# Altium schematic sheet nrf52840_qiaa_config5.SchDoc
size A4; Revision: 1.3; SheetNumber: 1; SheetTotal: 1; DrawnBy: RUBR; DocumentSize: A4; RefLayoutTitle: Reference Layout Config. 5: VDD supply, DCDC, USB, NFC; Device: nRF52840-QIAA
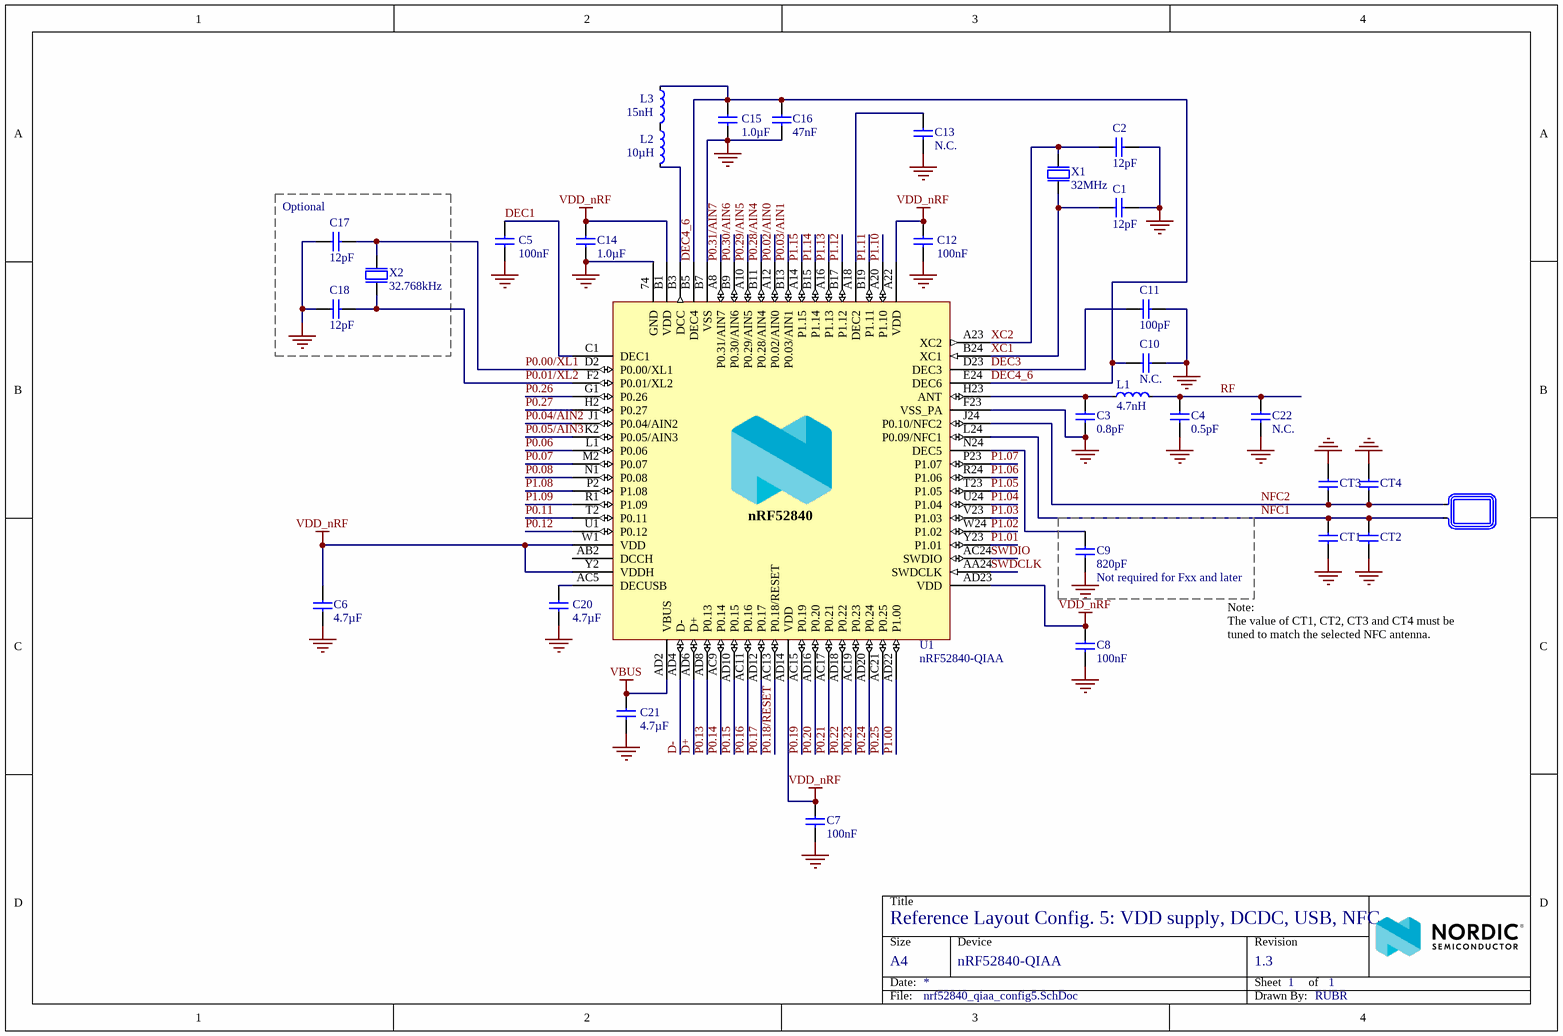
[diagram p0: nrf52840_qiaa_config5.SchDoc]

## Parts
A1  NFC Antenna  [TP_2x1mm_TH]  (value not drawn)  (no BOM)
C1  12pF  [CAPC1005X04L]
C2  12pF  [CAPC1005X04L]
C3  0.8pF  [CAPC1005X04L]
C4  0.5pF  [CAPC1005X04L]
C5  100nF  [CAPC1005X04L]
C6  4.7µF  [CAPC1608X06L]
C7  100nF  [CAPC1005X04L]
C8  100nF  [CAPC1005X04L]
C9  820pF  Assembly: Not required for Fxx and later  [CAPC1005X04L]
C10  N.C.  [CAPC1005X04L]
C11  100pF  [CAPC1005X04L]
C12  100nF  [CAPC1005X04L]
C13  N.C.  [CAPC1005X04L]
C14  1.0µF  [CAPC1608X06L]
C15  1.0µF  [CAPC1608X06L]
C16  47nF  [CAPC1005X04L]
C17  12pF  [CAPC1005X04L]
C18  12pF  [CAPC1005X04L]
C20  4.7µF  [CAPC1608X06L]
C21  4.7µF  [CAPC1608X06L]
C22  N.C.  [CAPC1005X04L]
CT1  Antenna dependent  [CAPC1005X04L]  (value not drawn)
CT2  Antenna dependent  [CAPC1005X04L]  (value not drawn)
CT3  Antenna dependent  [CAPC1005X04L]  (value not drawn)
CT4  Antenna dependent  [CAPC1005X04L]  (value not drawn)
L1  4.7nH  [INDC1005X04L]
L2  10µH  [INDC1608X06L]
L3  15nH  [INDC1005X04L]
U1  nRF52840-QIAA  [AQFN50P700X700X85_HS-74N]
X1  32MHz  [BT-XTAL_2016]
X2  32.768kHz  [XTAL_3215]

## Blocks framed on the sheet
Optional: C17 C18 X2

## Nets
GND: C1.2 C2.2 C3.1 C4.1 C5.2 C6.2 C7.2 C8.2 C9.2 C10.1 C11.2 C12.2 C13.2 C14.2 C15.1 C16.2 C17.2 C18.2 C20.2 C21.2 C22.2 CT1.2 CT2.2 CT3.1 CT4.1 U1.74(GND) U1.B7(VSS) U1.F23(VSS_PA) X1.2(GND) X1.4(GND)
VBUS: C21.1 U1.AD2(VBUS)
VDD_nRF: C6.1 C7.1 C8.1 C12.1 C14.1 U1.A22(VDD) U1.AD14(VDD) U1.AD23(VDD) U1.B1(VDD) U1.W1(VDD) U1.Y2(VDDH)
D+: U1.AD6(D+)
D-: U1.AD4(D-)
DEC1: C5.1 U1.C1(DEC1)
DEC3: C11.1 U1.D23(DEC3)
DEC4_6: C10.2 C15.2 C16.1 L3.1 U1.B5(DEC4) U1.E24(DEC6)
NFC1: A1.2 CT1.1 CT2.1 U1.L24(P0.09/NFC1)
NFC2: A1.1 CT3.2 CT4.2 U1.J24(P0.10/NFC2)
P0.00/XL1: C17.1 U1.D2(P0.00/XL1) X2.1(inp)
P0.01/XL2: C18.1 U1.F2(P0.01/XL2) X2.2(out)
P0.02/AIN0: U1.A12(P0.02/AIN0)
P0.03/AIN1: U1.B13(P0.03/AIN1)
P0.04/AIN2: U1.J1(P0.04/AIN2)
P0.05/AIN3: U1.K2(P0.05/AIN3)
P0.06: U1.L1(P0.06)
P0.07: U1.M2(P0.07)
P0.08: U1.N1(P0.08)
P0.11: U1.T2(P0.11)
P0.12: U1.U1(P0.12)
P0.13: U1.AD8(P0.13)
P0.14: U1.AC9(P0.14)
P0.15: U1.AD10(P0.15)
P0.16: U1.AC11(P0.16)
P0.17: U1.AD12(P0.17)
P0.18/RESET: U1.AC13(P0.18/RESET)
P0.19: U1.AC15(P0.19)
P0.20: U1.AD16(P0.20)
P0.21: U1.AC17(P0.21)
P0.22: U1.AD18(P0.22)
P0.23: U1.AC19(P0.23)
P0.24: U1.AD20(P0.24)
P0.25: U1.AC21(P0.25)
P0.26: U1.G1(P0.26)
P0.27: U1.H2(P0.27)
P0.28/AIN4: U1.B11(P0.28/AIN4)
P0.29/AIN5: U1.A10(P0.29/AIN5)
P0.30/AIN6: U1.B9(P0.30/AIN6)
P0.31/AIN7: U1.A8(P0.31/AIN7)
P1.00: U1.AD22(P1.00)
P1.01: U1.Y23(P1.01)
P1.02: U1.W24(P1.02)
P1.03: U1.V23(P1.03)
P1.04: U1.U24(P1.04)
P1.05: U1.T23(P1.05)
P1.06: U1.R24(P1.06)
P1.07: U1.P23(P1.07)
P1.08: U1.P2(P1.08)
P1.09: U1.R1(P1.09)
P1.10: U1.A20(P1.10)
P1.11: U1.B19(P1.11)
P1.12: U1.B17(P1.12)
P1.13: U1.A16(P1.13)
P1.14: U1.B15(P1.14)
P1.15: U1.A14(P1.15)
RF: C4.2 C22.1 L1.2
SWDCLK: U1.AA24(SWDCLK)
SWDIO: U1.AC24(SWDIO)
XC1: C1.1 U1.B24(XC1) X1.1(inp)
XC2: C2.1 U1.A23(XC2) X1.3(out)
NetC3_2: C3.2 L1.1 U1.H23(ANT)
NetC9_1: C9.1 U1.N24(DEC5)
NetC13_1: C13.1 U1.A18(DEC2)
NetC20_1: C20.1 U1.AC5(DECUSB)
NetL2_1: L2.1 L3.2
NetL2_2: L2.2 U1.B3(DCC)

Not connected (* = marked no-connect by the designer): U1 AB2(DCCH)

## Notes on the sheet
- Note:
  The value of CT1, CT2, CT3 and CT4 must be tuned to match the selected NFC antenna.

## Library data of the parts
A1 = NFC_ANT_TP: Pad Count: 2
C1 C2 C17 C18 = C0402-12p: Capacitor, NP0, ±2%; Pad Count: 2
C3 = C0402-0.8p: Capacitor, NP0, ±10%; Pad Count: 2
C4 = C0402-0.5p: Capacitor, NP0, ±10%; Pad Count: 2
C5 C7 C8 C12 = C0402-100n: Capacitor, X7R, ±10%; Pad Count: 2
C6 C20 = C0603-4µ7-6.3V-X7R: Capacitor, X7R, ±10%; Pad Count: 2
C9 = C0402-820p: Capacitor, NP0, ±5%; Pad Count: 2
C10 C13 C22 = C0402-N.C.: Not mounted; Pad Count: 2; Assembly: Not mounted
C11 = C0402-100p: Capacitor, NP0, ±5%; Pad Count: 2
C14 C15 = C0603-1µ0: Capacitor, X7R, ±10%; Pad Count: 2
C16 = C0402-47n: Capacitor, X7R, ±10%; Pad Count: 2
C21 = C0603-4µ7-10V-X7S: Capacitor, X7S, ±10%; Pad Count: 2
CT1-CT4 = C0402-TBD: Capacitor, NP0, ±5%; Pad Count: 2
L1 = L0402-4n7: High frequency chip inductor ±5%; Pad Count: 2
L2 = L0603-10µ: Chip inductor, IDC,min = 50 mA, ±20%; Pad Count: 2
L3 = L0402-15n: High frequency chip inductor ±10%; Pad Count: 2
U1 = nRF52840-QIAA: Multi-protocol Bluetooth Low Energy, IEEE 802.15.4, ANT and 2.4GHz proprietary system-on-chip; Pad Count: 73
X1 = XTAL_SMD2016_32MHz_8pF_General: XTAL SMD 2016, 32MHz, Cl=8pF, Total Tol: ±40ppm; Pad Count: 4
X2 = XTAL_SMD3215_32.768kHz_9pF_General: XTAL SMD 3215, 32.768kHz, Cl=9pF, Total Tol: ±50ppm; Pad Count: 2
